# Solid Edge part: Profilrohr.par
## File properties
Username: ahadarics
Dokumentum tartalom típus: 0
Author: ahadarics
Last saved by: ahadarics
Revision: 81
Sűrűség: 0,000 kg/m^3
Pontosság: 0,990
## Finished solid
Body 1: solid body, 6 faces, 6 edges, 0 vertices.
  Faces by surface: cone 2, cylinder 2, plane 2
  Edges by curve: circle 6
Bounding box of the edges (mm): 17.270 x 17.270 x 157.000, from (-8.635, -8.635, -136) to (8.635, 8.635, 21).
Cylindrical faces by radius (mm): R8 x1, R8.635 x1
Conical faces (half-angle, radius in mm at the cone's reference point): 15 deg R8.067 x2
Planar faces by outward normal: +z 1, -z 1
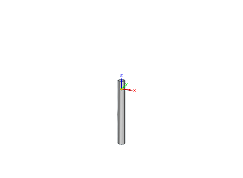
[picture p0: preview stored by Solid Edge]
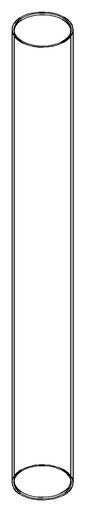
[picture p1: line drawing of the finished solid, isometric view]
